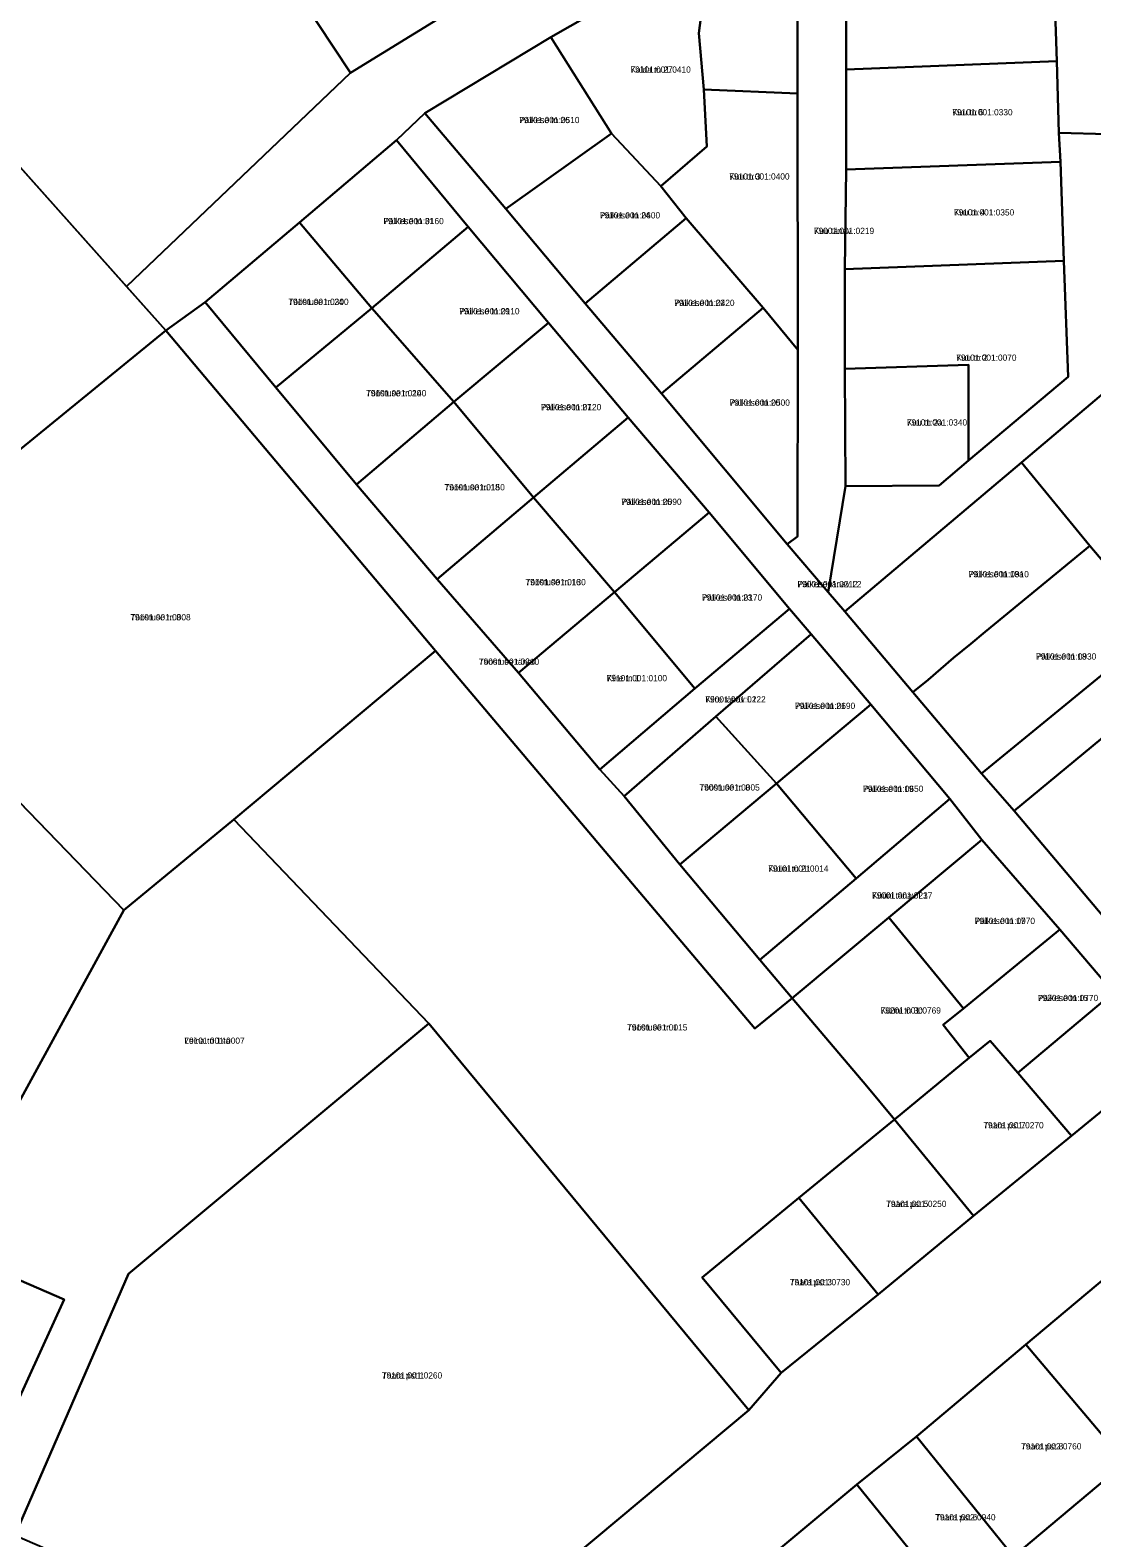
# Model space of a CAD drawing. Extents: x 587616 to 632239, y 6547421 to 6574977.
# Drawn here: x 611262 to 611517.4, y 6571731.9 to 6572094.4 of the extents above; entities that cross this region are included whole.
import ezdxf

# ---------------------------------------------------------------- set-up
doc = ezdxf.new("R2010")
doc.units = 0
for name, color, linetype in [('L_AADRESS', 7, 'Continuous'), ('PIIR', 7, 'Continuous'), ('TUNNUS', 7, 'Continuous')]:
    doc.layers.add(name, color=color, linetype=linetype)

msp = doc.modelspace()

# ---------------------------------------------------------------- linework, layer by layer
at = {"layer": 'PIIR'}
for points in [[(611443.8, 6572277.28), (611521.8, 6572183.91), (611384.89, 6572112.62), (611373.24, 6572132.7), (611370.16, 6572134.69), (611355.14, 6572135.39), (611342.09, 6572125.25), (611329.78, 6572119.16), (611329.78, 6572119.04), (611326.55, 6572108.65), (611327.11, 6572102.31), (611339.02, 6572084.19), (611285.16, 6572032.82), (611157, 6572176.63)], [(611425.52, 6572114.68), (611387.27, 6572092.73), (611356.95, 6572074.5), (611350.11, 6572067.95), (611326.76, 6572048.23), (611304.08, 6572029.07), (611294.64, 6572022.19), (611285.16, 6572032.82), (611339.02, 6572084.19), (611362.17, 6572098.35)], [(611522.57, 6571862.99), (611509.62, 6571878.21), (611490.9, 6571899.77), (611483.17, 6571909.57), (611464.17, 6571932.31), (611449.84, 6571949.16), (611444.62, 6571955.32), (611425.31, 6571978.49), (611405.8, 6572001.27), (611386.7, 6572024.05), (611367.35, 6572047.14), (611350.11, 6572067.95), (611356.95, 6572074.5), (611376.41, 6572051.45), (611395.51, 6572028.71), (611413.82, 6572007.04), (611444.09, 6571970.84), (611453.96, 6571959.32), (611457.96, 6571954.63), (611474.34, 6571935.26), (611490.78, 6571915.71), (611498.67, 6571906.72), (611521.13, 6571880.06)], [(611350.81, 6571692.38), (611434.88, 6571762.6), (611442.6, 6571771.6), (611465.95, 6571790.44), (611488.89, 6571809.32), (611512.43, 6571828.55), (611535.53, 6571847.46), (611543.01, 6571853.78), (611572.35, 6571877.96), (611602.84, 6571903.18), (611632.36, 6571927.58), (611662.57, 6571952.19), (611673.02, 6571960.92), (611691.91, 6571937.71), (611667.8, 6571917.67), (611632.8, 6571888.33), (611598.11, 6571859.14), (611563.05, 6571829.89), (611555.18, 6571823.56), (611528.32, 6571800.92), (611501.52, 6571778.34), (611475.22, 6571756.23), (611460.84, 6571744.72), (611438.7, 6571726.29)]]:
    msp.add_lwpolyline(points, dxfattribs=at)
for points in [[(610967.88, 6571757.58), (610865.98, 6571796.72), (610898.46, 6571877.96), (610924.78, 6571937.18), (610989.99, 6572059.08), (611157, 6572176.63), (611284.61, 6572033.44), (611294.62, 6572022.21), (611214.79, 6571957.15), (611146.84, 6571903.66), (611106.87, 6571869.36), (611080.99, 6571809.57), (611067.07, 6571801.69), (611051.66, 6571792.97), (611030.57, 6571761.03), (611016.03, 6571739.01)], [(611444.09, 6571970.84), (611446.54, 6571972.67), (611446.64, 6572017.59), (611446.54, 6572079.21), (611446.59, 6572117.54), (611442.54, 6572124.3), (611458.47, 6572130.71), (611458.37, 6572109.03), (611458.3, 6572084.97), (611458.26, 6572060.95), (611457.97, 6572036.97), (611457.97, 6572013), (611458.08, 6571984.75), (611453.96, 6571959.32)], [(611327.11, 6572102.31), (611326.55, 6572108.65), (611329.78, 6572119.04), (611329.78, 6572119.16), (611342.09, 6572125.25), (611346.17, 6572119.27), (611352.72, 6572108.72), (611355.04, 6572110.01), (611362.17, 6572098.35), (611339.02, 6572084.19)], [(611422.84, 6572093.68), (611425.52, 6572114.68), (611442.54, 6572124.3), (611446.59, 6572117.54), (611446.54, 6572079.21), (611424.03, 6572080.2)], [(611387.27, 6572092.73), (611425.52, 6572114.68), (611422.84, 6572093.68), (611424.03, 6572080.2), (611424.79, 6572066.45), (611413.68, 6572056.89), (611401.84, 6572069.62)], [(611458.3, 6572084.97), (611458.37, 6572109.03), (611484.43, 6572110.08), (611508.16, 6572110.87), (611508.95, 6572086.97)], [(611514.35, 6572103.88), (611530.95, 6572084.21), (611536.45, 6572077.46), (611528.14, 6572073.14), (611521.21, 6572069.41), (611509.45, 6572069.74), (611508.95, 6572086.97), (611508.16, 6572110.87)], [(611356.95, 6572074.5), (611387.27, 6572092.73), (611401.84, 6572069.62), (611376.41, 6572051.45)], [(611509.45, 6572069.74), (611509.8, 6572062.8), (611458.26, 6572060.95), (611458.3, 6572084.97), (611508.95, 6572086.97)], [(611446.64, 6572017.59), (611438.28, 6572027.63), (611419.76, 6572049.21), (611413.68, 6572056.89), (611424.79, 6572066.45), (611424.03, 6572080.2), (611446.54, 6572079.21)], [(611326.76, 6572048.23), (611350.11, 6572067.95), (611367.35, 6572047.14), (611344.15, 6572027.62)], [(611376.41, 6572051.45), (611401.84, 6572069.62), (611413.68, 6572056.89), (611419.76, 6572049.21), (611395.51, 6572028.71)], [(611509.8, 6572062.8), (611509.45, 6572069.74), (611521.21, 6572069.41), (611521.78, 6572046.81), (611522.49, 6572013.48), (611525.86, 6572011.98), (611521.23, 6572008.07), (611500.42, 6571990.5), (611457.96, 6571954.63), (611453.96, 6571959.31), (611458.08, 6571984.75), (611480.63, 6571984.97), (611487.68, 6571990.93), (611511.65, 6572011.07), (611510.65, 6572038.95)], [(611458.26, 6572060.95), (611509.8, 6572062.8), (611510.65, 6572038.95), (611457.97, 6572036.97)], [(611304.08, 6572029.07), (611326.76, 6572048.23), (611344.15, 6572027.62), (611321.08, 6572008.48)], [(611363.94, 6572005.08), (611344.15, 6572027.62), (611367.35, 6572047.14), (611386.7, 6572024.05)], [(611395.51, 6572028.71), (611419.76, 6572049.21), (611438.28, 6572027.63), (611413.82, 6572007.04)], [(611510.65, 6572038.95), (611511.65, 6572011.07), (611487.68, 6571990.93), (611487.72, 6572013.96), (611457.97, 6572013), (611457.97, 6572036.97)], [(611619.63, 6572021.02), (611640.94, 6572038.35), (611648.93, 6572029.28), (611618.64, 6572004.59), (611588.82, 6571980.13), (611558.21, 6571954.88), (611541.38, 6571941.51), (611527.85, 6571930.86), (611498.67, 6571906.72), (611490.78, 6571915.71), (611533.66, 6571950.72), (611555.19, 6571968.47), (611577.14, 6571985.89), (611598.02, 6572003.32)], [(611304.08, 6572029.07), (611321.08, 6572008.48), (611340.51, 6571985.17), (611359.92, 6571962.46), (611379.47, 6571939.88), (611399.04, 6571916.63), (611404.89, 6571910.21), (611418.28, 6571893.8), (611437.5, 6571870.9), (611445.25, 6571861.67), (611436.28, 6571854.34), (611359.46, 6571945.18), (611294.62, 6572022.21)], [(611321.08, 6572008.48), (611344.15, 6572027.62), (611363.94, 6572005.08), (611340.51, 6571985.17)], [(611438.28, 6572027.63), (611446.64, 6572017.59), (611446.54, 6571972.67), (611444.09, 6571970.84), (611413.82, 6572007.04)], [(611294.62, 6572022.21), (611359.46, 6571945.18), (611311.01, 6571904.61), (611284.53, 6571882.81), (611241.06, 6571927.72), (611214.79, 6571957.15)], [(611363.94, 6572005.08), (611386.7, 6572024.05), (611405.8, 6572001.27), (611383.06, 6571982.04)], [(611457.97, 6572013), (611487.72, 6572013.96), (611487.68, 6571990.93), (611480.63, 6571984.97), (611458.08, 6571984.75)], [(611500.42, 6571990.5), (611521.23, 6572008.07), (611555.19, 6571968.47), (611533.66, 6571950.72), (611516.87, 6571970.44)], [(611340.51, 6571985.17), (611363.94, 6572005.08), (611383.06, 6571982.04), (611359.92, 6571962.46)], [(611425.31, 6571978.49), (611402.52, 6571959.26), (611383.06, 6571982.04), (611405.8, 6572001.27)], [(611516.87, 6571970.44), (611491.72, 6571949.74), (611488.26, 6571946.91), (611484.06, 6571943.51), (611478.02, 6571938.23), (611474.34, 6571935.26), (611457.96, 6571954.63), (611500.42, 6571990.5)], [(611359.92, 6571962.46), (611383.06, 6571982.04), (611402.52, 6571959.26), (611379.47, 6571939.88)], [(611402.52, 6571959.26), (611425.31, 6571978.49), (611444.62, 6571955.32), (611421.9, 6571936.11)], [(611474.34, 6571935.26), (611478.02, 6571938.23), (611484.06, 6571943.51), (611488.26, 6571946.91), (611491.72, 6571949.74), (611516.87, 6571970.44), (611533.66, 6571950.72), (611490.78, 6571915.71)], [(611421.9, 6571936.11), (611399.04, 6571916.63), (611379.47, 6571939.88), (611402.52, 6571959.26)], [(611214.79, 6571957.15), (611241.06, 6571927.72), (611284.53, 6571882.81), (611240.34, 6571802.08), (611270.16, 6571789.21), (611246.61, 6571737.64), (611080.99, 6571809.57), (611106.87, 6571869.36), (611146.84, 6571903.66)], [(611421.9, 6571936.11), (611444.62, 6571955.32), (611449.84, 6571949.16), (611426.91, 6571929.37), (611404.89, 6571910.21), (611399.04, 6571916.63)], [(611426.91, 6571929.37), (611449.84, 6571949.16), (611464.17, 6571932.31), (611441.48, 6571913.25)], [(611359.46, 6571945.18), (611436.28, 6571854.34), (611445.25, 6571861.67), (611463.24, 6571840.52), (611469.89, 6571832.5), (611446.89, 6571813.63), (611423.67, 6571794.53), (611442.6, 6571771.6), (611434.88, 6571762.6), (611357.86, 6571855.59), (611311.01, 6571904.61)], [(611441.48, 6571913.25), (611464.17, 6571932.31), (611483.17, 6571909.57), (611460.7, 6571890.4)], [(611498.67, 6571906.72), (611527.85, 6571930.86), (611550.17, 6571904.12), (611521.13, 6571880.06)], [(611426.91, 6571929.37), (611441.48, 6571913.25), (611418.28, 6571893.8), (611404.89, 6571910.21)], [(611441.48, 6571913.25), (611460.7, 6571890.4), (611437.5, 6571870.9), (611418.28, 6571893.8)], [(611460.7, 6571890.4), (611483.17, 6571909.57), (611490.9, 6571899.77), (611468.56, 6571881.07), (611445.25, 6571861.67), (611437.5, 6571870.9)], [(611311.01, 6571904.61), (611357.86, 6571855.59), (611285.64, 6571795.35), (611258.33, 6571732.44), (611246.61, 6571737.64), (611270.16, 6571789.21), (611240.34, 6571802.08), (611284.53, 6571882.81)], [(611468.56, 6571881.07), (611490.9, 6571899.77), (611509.62, 6571878.21), (611486.49, 6571859.2)], [(611463.24, 6571840.52), (611445.25, 6571861.67), (611468.56, 6571881.07), (611486.49, 6571859.2), (611481.6, 6571855.29), (611487.85, 6571847.3), (611469.89, 6571832.5)], [(611486.49, 6571859.2), (611509.62, 6571878.21), (611522.57, 6571862.99), (611499.56, 6571843.7), (611492.89, 6571851.4), (611487.85, 6571847.3), (611481.6, 6571855.29)], [(611499.56, 6571843.7), (611522.57, 6571862.99), (611535.53, 6571847.46), (611512.43, 6571828.55)], [(611434.88, 6571762.6), (611350.81, 6571692.38), (611258.33, 6571732.44), (611285.64, 6571795.35), (611357.86, 6571855.59)], [(611499.56, 6571843.7), (611512.43, 6571828.55), (611488.89, 6571809.32), (611469.89, 6571832.5), (611487.85, 6571847.3), (611492.89, 6571851.4)], [(611446.89, 6571813.63), (611469.89, 6571832.5), (611488.89, 6571809.32), (611465.95, 6571790.44)], [(611442.6, 6571771.6), (611423.67, 6571794.53), (611446.89, 6571813.63), (611465.95, 6571790.44)], [(611539.08, 6571761.41), (611525.48, 6571749.97), (611501.52, 6571778.34), (611528.32, 6571800.92), (611552.25, 6571772.58)], [(611475.22, 6571756.23), (611501.52, 6571778.34), (611525.48, 6571749.97), (611498.55, 6571727.41)], [(611475.22, 6571756.23), (611498.55, 6571727.41), (611484.34, 6571715.72), (611460.84, 6571744.72)], [(611522.47, 6571699.21), (611498.55, 6571727.41), (611525.48, 6571749.97), (611549.36, 6571721.82)], [(611460.84, 6571744.72), (611484.34, 6571715.72), (611472.08, 6571705.27), (611462.49, 6571697.1), (611438.7, 6571726.29)]]:
    msp.add_lwpolyline(points, close=True, dxfattribs=at)

# ---------------------------------------------------------------- texts
at = {"layer": 'L_AADRESS'}
for s, p in [('Kalda tn 27', (611406.4, 6572084.21)), ('Kuu tn 6', (611483.8, 6572073.96)), ('Päikese tn 26', (611379.63, 6572072.09)), ('Kuu tn 3', (611430.16, 6572058.51)), ('Päikese tn 24', (611399.02, 6572049.17)), ('Kuu tn 4', (611484.19, 6572049.88)), ('Päikese tn 31', (611346.98, 6572047.79)), ('Kuu tänav', (611450.5, 6572045.43)), ('Tööstuse tn 24', (611324.1, 6572028.36)), ('Päikese tn 22', (611416.93, 6572028.12)), ('Päikese tn 29', (611365.22, 6572026.11)), ('Kuu tn 2', (611484.74, 6572014.94)), ('Tööstuse tn 20', (611342.8, 6572006.4)), ('Päikese tn 27', (611384.87, 6572003.05)), ('Päikese tn 20', (611430.23, 6572004.13)), ('Kuu tn 2a', (611472.86, 6571999.36)), ('Tööstuse tn 18', (611361.67, 6571983.77)), ('Päikese tn 25', (611404.19, 6571980.28)), ('Päikese tn 18a', (611487.71, 6571962.88)), ('Tööstuse tn 16', (611381.14, 6571960.96)), ('Päikese tänav L2', (611446.56, 6571960.49)), ('Päikese tn 23', (611423.57, 6571957.27)), ('Tööstuse tn 3', (611286.11, 6571952.51)), ('Päikese tn 18', (611503.93, 6571943.08)), ('Tööstuse tänav', (611369.93, 6571941.84)), ('Kiire tn 1', (611400.68, 6571937.87)), ('Kiire tänav L1', (611424.41, 6571932.77)), ('Päikese tn 21', (611445.95, 6571931.21)), ('Tööstuse tn 8', (611422.98, 6571911.59)), ('Päikese tn 19', (611462.32, 6571911.27)), ('Küüni tn 21', (611439.51, 6571892.07)), ('Küüni tänav L3', (611464.5, 6571885.62)), ('Päikese tn 17', (611489.19, 6571879.49)), ('Päikese tn 15', (611504.38, 6571860.96)), ('Küüni tn 30', (611466.55, 6571857.96)), ('Tööstuse tn 1', (611405.57, 6571853.89)), ('Leina tn 14a', (611299.1, 6571850.69)), ('Taara pst 7', (611491.27, 6571830.36)), ('Taara pst 5', (611467.89, 6571811.45)), ('Taara pst 3', (611444.71, 6571792.62)), ('Taara pst 1', (611346.61, 6571770.2)), ('Taara pst 8', (611500.35, 6571753.14)), ('Taara pst 6', (611479.7, 6571736.08))]:
    msp.add_text(s, height=1.5, dxfattribs=at).set_placement(p)
at = {"layer": 'TUNNUS'}
for s, p in [('79101:001:0410', (611406.4, 6572084.21)), ('79101:001:0330', (611483.8, 6572073.96)), ('79101:001:0510', (611379.63, 6572072.09)), ('79101:001:0400', (611430.16, 6572058.51)), ('79101:001:0600', (611399.02, 6572049.17)), ('79101:001:0350', (611484.19, 6572049.88)), ('79101:001:0160', (611346.98, 6572047.79)), ('79001:001:0219', (611450.5, 6572045.43)), ('79101:001:0300', (611324.1, 6572028.36)), ('79101:001:0420', (611416.93, 6572028.12)), ('79101:001:0110', (611365.22, 6572026.11)), ('79101:001:0070', (611484.74, 6572014.94)), ('79101:001:0140', (611342.8, 6572006.4)), ('79101:001:0120', (611384.87, 6572003.05)), ('79101:001:0500', (611430.23, 6572004.13)), ('79101:001:0340', (611472.86, 6571999.36)), ('79101:001:0150', (611361.67, 6571983.77)), ('79101:001:0090', (611404.19, 6571980.28)), ('79101:001:0910', (611487.71, 6571962.88)), ('79101:001:0130', (611381.14, 6571960.96)), ('79001:001:0212', (611446.56, 6571960.49)), ('79101:001:0170', (611423.57, 6571957.27)), ('79101:001:0008', (611286.11, 6571952.51)), ('79101:001:0930', (611503.93, 6571943.08)), ('79001:001:0210', (611369.93, 6571941.84)), ('79101:001:0100', (611400.68, 6571937.87)), ('79001:001:0222', (611424.41, 6571932.77)), ('79101:001:0690', (611445.95, 6571931.21)), ('79001:001:0005', (611422.98, 6571911.59)), ('79101:001:0650', (611462.32, 6571911.27)), ('79101:001:0014', (611439.51, 6571892.07)), ('79001:001:0217', (611464.5, 6571885.62)), ('79101:001:0970', (611489.19, 6571879.49)), ('79201:001:0770', (611504.38, 6571860.96)), ('79201:001:0769', (611466.55, 6571857.96)), ('79101:001:0015', (611405.57, 6571853.89)), ('79101:001:0007', (611299.1, 6571850.69)), ('79101:001:0270', (611491.27, 6571830.36)), ('79101:001:0250', (611467.89, 6571811.45)), ('79101:001:0730', (611444.71, 6571792.62)), ('79101:001:0260', (611346.61, 6571770.2)), ('79101:002:0760', (611500.35, 6571753.14)), ('79101:002:0940', (611479.7, 6571736.08))]:
    msp.add_text(s, height=1.5, dxfattribs=at).set_placement(p)

doc.saveas('drawing.dxf')
